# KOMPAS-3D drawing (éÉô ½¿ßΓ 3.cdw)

Referenced files: ВРУ лист 3.cdw
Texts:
  Электроснабжение первой детской клинической больницы  по адресу: г. Иваново, ул. Мальцева д.3 (Главный корпус)
  Casper
  Текст на чертеже
  Размерные надписи
  Шероховатость
  Линия-выноска #1
  Линия-выноска #2
  Линия-выноска #3
  Отклонения формы и база
  Заголовок таблицы
  Ячейка таблицы
  Стрелка вида
  Обозначение изменения
  Фигурная скобка
  Номер узла
  Марка координационной оси
  VRCB
  Выносная надпись
  Обозначение узла
  Марка/позиционное обозначение с линией-выноской
  Марка/позиционное обозначение на линии
  Марка/позиционное обозначение без линии-выноски
  Номер группы
  Р кВт
  Ток, А
  Гр1
  Гр2
  Гр3
  Гр4
  ВА 47-29 (3)
  к заземлителю
  ПВ 1х16 мм 2
  ВРУ (ЩМП-7)
  Гр5
  Щиток РЩ10
  Щиток РЩ11
  Щиток РЩ12
  Щиток РЩ13
  Щиток РЩ14
  ВВГнгLS 5х10 мм2 скрыто
  в гофр. ПВХ трубе
  ВА 47-29 (1)
  ВВГнгLS 5х16 мм2 скрыто
  Щиток ОПС
  Щиток ЩВ 1
  Щиток ЩВ 2
  Гр6
  Гр7
  Гр8
  к звводимым коммуникациям
  CONTINUOUS0
  Электроснабжение первой детской клинической больницы
  по адресу: г. Иваново, ул. Мальцева д.3 (Главный корпус)
  Однолинейная схема ВРУ лист 3
  ГИП
  Кочетков
  Разработ
  ООО "Мастер Лайт"
Dimensions and other numbers on the sheet: 2012-0011-ЭС; 7; 5.0; 16А; 7.9; 25А; 0.2; 1.3; 7.0; 14.9; 4; 1:1; 1; 5; 0; 2; 3; 6; 8; 9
